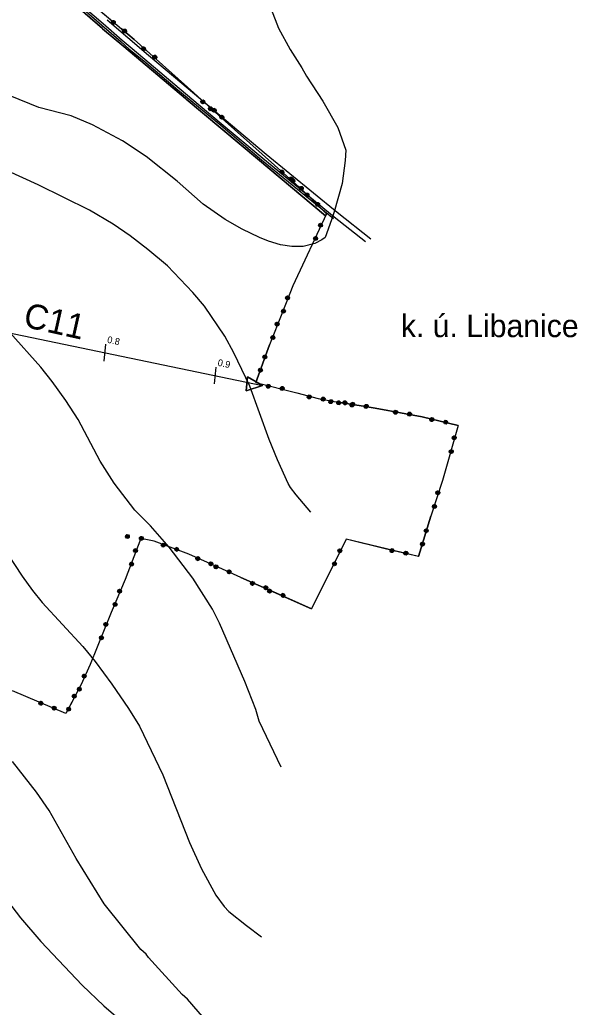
# Model space of a CAD drawing. Extents: x -645676 to -642474, y -1077513 to -1072613.
# Drawn here: x -642993 to -642499, y -1074361 to -1073486 of the extents above; entities that cross this region are included whole.
import ezdxf

# ---------------------------------------------------------------- set-up
doc = ezdxf.new("R2010")
doc.units = 0
for name, color, linetype in [('katastr_ln___zem____popis', 7, 'Continuous'), ('KULTURY_STAV', 7, 'Continuous'), ('OBVOD_PU', 7, 'Continuous'), ('P__kop___st_vaj_c_', 7, 'Continuous'), ('PC_NAVRH', 7, 'Continuous'), ('PC_POPIS_NAVRH', 7, 'Continuous'), ('PC_STAN_NAVRH', 7, 'Continuous'), ('Silnice_II__t__dy_a_III__t__dy', 7, 'Continuous'), ('SPRAV_HR_STAV', 7, 'Continuous'), ('VRSTEVNICE', 7, 'Continuous')]:
    doc.layers.add(name, color=color, linetype=linetype)

# ---------------------------------------------------------------- blocks, each defined once
blk = doc.blocks.new('$944')
blk.add_line((0, 1.5), (0, -1.5))
blk = doc.blocks.new('$920')
for points in [[(0, 0), (-2.8, 1.25), (-2.8, -1.25), (0, 0)], [(-2.8, 1.25), (0, 0), (-2.8, -1.25), (-2.8, 1.25)]]:
    blk.add_lwpolyline(points)
blk = doc.blocks.new('2$0620')
for points in [[(-1.07, 0.32), (-0.88, 0.13), (-0.88, -0.14), (-1.07, -0.33), (-1.34, -0.33), (-1.53, -0.14), (-1.53, 0.13), (-1.34, 0.32), (-1.07, 0.32), (-1.08, 0.28), (-1.32, 0.28), (-1.4, 0.2), (-1, 0.2), (-0.92, 0.12), (-1.48, 0.12), (-1.48, 0.04), (-0.92, 0.04), (-0.92, -0.04), (-1.48, -0.04), (-1.48, -0.12), (-0.92, -0.12), (-1, -0.2), (-1.4, -0.2), (-1.32, -0.28), (-1.08, -0.28)], [(1.43, 0.32), (1.62, 0.13), (1.62, -0.14), (1.43, -0.33), (1.16, -0.33), (0.97, -0.14), (0.97, 0.13), (1.16, 0.32), (1.43, 0.32), (1.4, 0.28), (1.16, 0.28), (1.08, 0.2), (1.48, 0.2), (1.56, 0.12), (1, 0.12), (1, 0.04), (1.56, 0.04), (1.56, -0.04), (1, -0.04), (1, -0.12), (1.56, -0.12), (1.48, -0.2), (1.08, -0.2), (1.16, -0.28), (1.4, -0.28)]]:
    blk.add_lwpolyline(points)

msp = doc.modelspace()

# ---------------------------------------------------------------- linework, layer by layer
at = {"layer": 'KULTURY_STAV'}
for points in [[(-642972.5, -1073447.63), (-642919.91, -1073493.56), (-642919.87, -1073493.59), (-642901.19, -1073509.35), (-642900.99, -1073509.52), (-642846.38, -1073555.54), (-642845.81, -1073556.02), (-642782.62, -1073608.9), (-642782.38, -1073609.11), (-642733.3, -1073650.5), (-642722.15, -1073659.46), (-642721.3, -1073657.64), (-642751.17, -1073721.72), (-642760.43, -1073745.06), (-642771.94, -1073773.87), (-642783.93, -1073807.14), (-642747.64, -1073816.53), (-642728.65, -1073821.54), (-642711.31, -1073824.82), (-642686.87, -1073828.69), (-642674.89, -1073830.57), (-642636.52, -1073837.75), (-642604.57, -1073845.43), (-642618.62, -1073894.26), (-642628.8, -1073925.8), (-642639.88, -1073961.58), (-642669.19, -1073954.61), (-642704.02, -1073946.33), (-642734.6, -1074008), (-642768.29, -1073993.02), (-642782.04, -1073986.91), (-642797.33, -1073980.11), (-642813.53, -1073972.91), (-642843.55, -1073959.52), (-642874.27, -1073947.97), (-642886.05, -1073945.72), (-642899.89, -1073981.87), (-642912.36, -1074011.3), (-642930.99, -1074057.3), (-642939.28, -1074075.5), (-642951.32, -1074098.58), (-642952.44, -1074100.73), (-642999.74, -1074080.7)], [(-642950.44, -1073453.5), (-642903.06, -1073493.73), (-642891.8, -1073503.23), (-642839.12, -1073550.41), (-642832.29, -1073556.56), (-642813.86, -1073573.17), (-642742.8, -1073636.35), (-642735.62, -1073643.46), (-642721.3, -1073657.64), (-642722.15, -1073659.46), (-642733.3, -1073650.5), (-642782.38, -1073609.11), (-642782.62, -1073608.9), (-642845.81, -1073556.02), (-642846.38, -1073555.54), (-642900.99, -1073509.52), (-642901.19, -1073509.35), (-642919.87, -1073493.59), (-642919.91, -1073493.56), (-642972.5, -1073447.63)]]:
    msp.add_lwpolyline(points, dxfattribs=at)
at = {"layer": 'OBVOD_PU'}
msp.add_lwpolyline([(-642950.44, -1073453.5), (-642903.06, -1073493.73), (-642891.8, -1073503.23), (-642839.12, -1073550.41), (-642832.29, -1073556.56), (-642813.86, -1073573.17), (-642742.8, -1073636.35), (-642735.62, -1073643.46), (-642721.3, -1073657.64), (-642751.17, -1073721.72), (-642760.43, -1073745.06), (-642771.94, -1073773.87), (-642783.93, -1073807.14), (-642747.64, -1073816.53), (-642728.65, -1073821.54), (-642711.31, -1073824.82), (-642686.87, -1073828.69), (-642674.89, -1073830.57), (-642636.52, -1073837.75), (-642604.57, -1073845.43), (-642618.62, -1073894.26), (-642628.8, -1073925.8), (-642639.88, -1073961.58), (-642704.02, -1073946.33), (-642734.6, -1074008), (-642782.04, -1073986.91), (-642797.33, -1073980.11), (-642813.53, -1073972.91), (-642843.55, -1073959.52), (-642874.27, -1073947.97), (-642886.05, -1073945.72), (-642899.89, -1073981.87), (-642912.36, -1074011.3), (-642930.99, -1074057.3), (-642939.28, -1074075.5), (-642952.44, -1074100.73), (-642999.74, -1074080.7)], dxfattribs=at)
at = {"layer": 'P__kop___st_vaj_c_'}
msp.add_lwpolyline([(-642946.02, -1073468.22), (-642920.53, -1073490.33), (-642903.65, -1073505.07), (-642896.31, -1073511.82), (-642883.41, -1073522.17), (-642853.25, -1073547.89), (-642815.13, -1073579.2), (-642778.88, -1073609.74), (-642715.19, -1073662.02)], dxfattribs=at)
at = {"layer": 'PC_NAVRH'}
msp.add_lwpolyline([(-643651.3, -1073746.65), (-643642.16, -1073747.03), (-643634.9, -1073748.9), (-643627.26, -1073738.26), (-643603.35, -1073720.23), (-643590.34, -1073707.33), (-643581.82, -1073694.43), (-643570.81, -1073681.9), (-643563.42, -1073670.01), (-643558.29, -1073648.59), (-643471.17, -1073665.87), (-643315.58, -1073698.56), (-643063.81, -1073750.46), (-642778.16, -1073809.87)], dxfattribs=at)
at = {"layer": 'Silnice_II__t__dy_a_III__t__dy'}
for p, q in [((-642919.47, -1073489.38), (-642945.46, -1073466.95)), ((-642915.88, -1073485.66), (-642879.26, -1073516.95)), ((-642902.44, -1073504.03), (-642919.47, -1073489.38)), ((-642895.41, -1073510.01), (-642902.44, -1073504.03)), ((-642882.36, -1073520.96), (-642895.41, -1073510.01)), ((-642852.1, -1073546.56), (-642882.36, -1073520.96)), ((-642879.26, -1073516.95), (-642849.69, -1073542.04)), ((-642814.6, -1073577.93), (-642852.1, -1073546.56)), ((-642849.69, -1073542.04), (-642812, -1073573.5)), ((-642812, -1073573.5), (-642774.73, -1073604.77)), ((-642777.87, -1073608.73), (-642814.6, -1073577.93)), ((-642774.73, -1073604.77), (-642712.02, -1073656.36)), ((-642714.55, -1073660.78), (-642777.87, -1073608.73)), ((-642686.73, -1073682.63), (-642714.55, -1073660.78)), ((-642712.02, -1073656.36), (-642682.01, -1073679.78))]:
    msp.add_line(p, q, dxfattribs=at)
at = {"layer": 'SPRAV_HR_STAV'}
for p, q in [((-642950.44, -1073453.5), (-642903.06, -1073493.73)), ((-642891.8, -1073503.23), (-642903.06, -1073493.73)), ((-642891.8, -1073503.23), (-642839.12, -1073550.41)), ((-642839.12, -1073550.41), (-642832.29, -1073556.56)), ((-642832.29, -1073556.56), (-642813.86, -1073573.17)), ((-642742.8, -1073636.35), (-642813.86, -1073573.17)), ((-642735.62, -1073643.46), (-642742.8, -1073636.35)), ((-642721.3, -1073657.64), (-642735.62, -1073643.46)), ((-642721.3, -1073657.64), (-642751.17, -1073721.72)), ((-642751.17, -1073721.72), (-642760.43, -1073745.06)), ((-642760.43, -1073745.06), (-642771.94, -1073773.87)), ((-642783.93, -1073807.14), (-642771.94, -1073773.87)), ((-642783.93, -1073807.14), (-642747.64, -1073816.53)), ((-642747.64, -1073816.53), (-642728.65, -1073821.54)), ((-642728.65, -1073821.54), (-642711.31, -1073824.82)), ((-642686.87, -1073828.69), (-642711.31, -1073824.82)), ((-642674.89, -1073830.57), (-642686.87, -1073828.69)), ((-642636.52, -1073837.75), (-642674.89, -1073830.57)), ((-642604.57, -1073845.43), (-642636.52, -1073837.75)), ((-642604.57, -1073845.43), (-642618.62, -1073894.26)), ((-642618.62, -1073894.26), (-642628.8, -1073925.8)), ((-642639.88, -1073961.58), (-642628.8, -1073925.8)), ((-642886.05, -1073945.72), (-642899.89, -1073981.87)), ((-642874.27, -1073947.97), (-642886.05, -1073945.72)), ((-642843.55, -1073959.52), (-642874.27, -1073947.97)), ((-642704.02, -1073946.33), (-642734.6, -1074008)), ((-642639.88, -1073961.58), (-642704.02, -1073946.33)), ((-642813.53, -1073972.91), (-642843.55, -1073959.52)), ((-642797.33, -1073980.11), (-642813.53, -1073972.91)), ((-642899.89, -1073981.87), (-642912.36, -1074011.3)), ((-642797.33, -1073980.11), (-642782.04, -1073986.91)), ((-642782.04, -1073986.91), (-642734.6, -1074008)), ((-642912.36, -1074011.3), (-642930.99, -1074057.3)), ((-642930.99, -1074057.3), (-642939.28, -1074075.5)), ((-642952.44, -1074100.73), (-642999.74, -1074080.7)), ((-642939.28, -1074075.5), (-642952.44, -1074100.73))]:
    msp.add_line(p, q, dxfattribs=at)
at = {"layer": 'VRSTEVNICE'}
for points in [[(-642770.53, -1073476.26), (-642763.83, -1073493.01), (-642753.58, -1073511.96), (-642743.06, -1073528.29), (-642739.19, -1073535.6), (-642724.67, -1073557.82), (-642711.36, -1073581.3), (-642704.27, -1073601.3), (-642704.79, -1073610.59), (-642707.44, -1073630.83), (-642714.41, -1073655.94), (-642716.83, -1073663.21), (-642722.66, -1073678.87), (-642725.38, -1073680.87), (-642731.65, -1073684.14), (-642741.9, -1073686.71), (-642752.15, -1073686.85), (-642762.27, -1073685.28), (-642772.7, -1073682.1), (-642780.64, -1073678.59), (-642796.02, -1073671.33), (-642811.12, -1073662.78), (-642830.77, -1073649.11), (-642853.7, -1073628.74), (-642881.19, -1073606.95), (-642902.27, -1073593.14), (-642928.76, -1073578.89), (-642947.84, -1073570.92), (-642976.33, -1073563.51), (-643001.96, -1073553.12)], [(-642735.18, -1073922.15), (-642748.28, -1073906.78), (-642753.15, -1073900.34), (-642755.29, -1073896.78), (-642764.9, -1073875.9), (-642772.24, -1073857.9), (-642789.18, -1073810.47), (-642803.43, -1073780.99), (-642811.4, -1073766.32), (-642829.63, -1073739.55), (-642839.74, -1073727.44), (-642862.39, -1073703.94), (-642879.62, -1073689.27), (-642895.29, -1073677.31), (-642910.38, -1073666.77), (-642931.61, -1073654.38), (-642976.9, -1073632.16), (-643004.24, -1073619.63)], [(-642761.39, -1074148.28), (-642780.92, -1074107.42), (-642784.06, -1074097.17), (-642793.74, -1074072.38), (-642816.24, -1074020.54), (-642822.51, -1074008.15), (-642839.89, -1073980.67), (-642860.82, -1073953.32), (-642877.49, -1073934.38), (-642891.19, -1073920.39), (-642909.67, -1073896.64), (-642921.92, -1073876.98), (-642941.57, -1073839.95), (-642952.4, -1073823.15), (-642964.5, -1073806.34), (-642974.76, -1073793.81), (-643002.1, -1073763.04)], [(-643340.18, -1073899.06), (-643332.66, -1073901.76), (-643282.53, -1073921.42), (-643259.74, -1073933.24), (-643241.51, -1073945.63), (-643227.56, -1073957.45), (-643214.6, -1073969.56), (-643206.34, -1073979.38), (-643188.53, -1074008.86), (-643169.16, -1074047.6), (-643160.48, -1074062.13), (-643136.41, -1074097.74), (-643116.61, -1074123.66), (-643104.93, -1074137.75), (-643074.88, -1074170.51), (-643046.97, -1074205.12), (-643008.8, -1074260.67), (-642992.7, -1074282.03), (-642974.76, -1074302.96), (-642937.87, -1074341.56), (-642918.65, -1074359.93), (-642874.35, -1074397.96), (-642851.28, -1074420.6), (-642800.28, -1074483.73)], [(-643018.62, -1073937.65), (-642991.28, -1073978.96), (-642982.02, -1073991.77), (-642973.33, -1074002.46), (-642937.44, -1074041.34), (-642926.48, -1074054.72), (-642911.67, -1074074.66), (-642896.85, -1074096.31), (-642887.03, -1074111.98), (-642866.38, -1074155.27), (-642842.73, -1074215.09), (-642832.3, -1074238.61), (-642819.38, -1074261.8), (-642811.97, -1074271.92), (-642807.84, -1074276.19), (-642792.24, -1074288.66), (-642778.85, -1074298.89)], [(-642825.71, -1074376.01), (-642844.73, -1074354.09), (-642849.29, -1074349.82), (-642879.19, -1074317.21), (-642881.33, -1074314.22), (-642885.95, -1074309.84), (-642918.5, -1074269.35), (-642943.43, -1074229.33), (-642967.21, -1074186.89), (-642978.6, -1074170.37), (-642999.83, -1074143.17)]]:
    msp.add_lwpolyline(points, dxfattribs=at)

# ---------------------------------------------------------------- block references
at = {"layer": 'PC_STAN_NAVRH', "xscale": 5.000000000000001, "yscale": 5, "rotation": -5.67241100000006}
for name, p in [('$944', (-642917.98, -1073780.79)), ('$944', (-642820.07, -1073801.15)), ('$920', (-642778.16, -1073809.87))]:
    msp.add_blockref(name, p, dxfattribs=at)
at = {"layer": 'SPRAV_HR_STAV'}
for p, xscale, yscale, rotation in [((-642905.18, -1073491.95), 5, 5, 142.286626), ((-642878.76, -1073514.91), 4.999999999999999, 5, -36.29468500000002), ((-642826.12, -1073562.12), 5, 5, -36.45099100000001), ((-642819.29, -1073568.28), 5, 5, -36.47700900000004), ((-642755.88, -1073624.72), 5, 5, 140.774284), ((-642748.05, -1073631.15), 5, 5, 137.64176), ((-642733.74, -1073645.33), 4.999999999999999, 5, 137.642552), ((-642728.69, -1073673.5), 5, 5.000000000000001, -110.715737), ((-642757.62, -1073737.99), 5, 5, -107.305695), ((-642766.92, -1073761.31), 5.000000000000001, 4.999999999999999, -107.44510000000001), ((-642778, -1073790.68), 5, 4.999999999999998, 71.406515), ((-642766.99, -1073811.52), 5, 5.000000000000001, -8.477077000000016), ((-642730.72, -1073820.99), 5, 4.999999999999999, -8.753967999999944), ((-642711.45, -1073824.79), 5, 5.000000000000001, -4.615157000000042), ((-642704.15, -1073825.95), 5, 5, 173.986641), ((-642692.18, -1073827.86), 5, 4.999999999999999, 174.067351), ((-642653.72, -1073834.53), 5, 5, 172.357688), ((-642621.59, -1073841.34), 5, 4.999999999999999, 169.389614), ((-642609.41, -1073862.25), 4.999999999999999, 5.000000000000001, -101.62005900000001), ((-642624, -1073910.91), 5, 5.000000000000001, -103.48805700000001), ((-642634.7, -1073944.86), 5.000000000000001, 5, 74.064298), ((-642891.46, -1073944.69), 5, 4.999999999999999, 172.139519), ((-642859.93, -1073953.36), 5, 5, 162.176889), ((-642892.31, -1073962.06), 5, 4.999999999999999, -106.602555), ((-642711.79, -1073962.01), 4.999999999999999, 4.999999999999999, -112.123157), ((-642656.91, -1073957.53), 4.999999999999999, 4.999999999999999, 169.533786), ((-642829.51, -1073965.78), 4.999999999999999, 4.999999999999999, 158.68345399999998), ((-642813.32, -1073973), 5.000000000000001, 4.999999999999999, 158.760884), ((-642781.34, -1073987.22), 5, 5.000000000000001, -18.111667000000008), ((-642906.72, -1073997.98), 5, 5, -108.651599), ((-642766.05, -1073994.02), 4.999999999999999, 4.999999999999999, -18.103216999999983), ((-642918.93, -1074027.52), 5, 5, -107.72038000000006), ((-642938.24, -1074073.23), 5, 5, -110.20403900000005), ((-642968.55, -1074093.91), 5.000000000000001, 4.999999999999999, 159.789951), ((-642947.37, -1074091.02), 5, 5, -113.31497900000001)]:
    msp.add_blockref('2$0620', p, dxfattribs=dict(at, xscale=xscale, yscale=yscale, rotation=rotation))

# ---------------------------------------------------------------- texts
at = {"layer": 'katastr_ln___zem____popis'}
msp.add_text('k. ú. Libanice', height=20, dxfattribs=at).set_placement((-642655.39, -1073767.07))
at = {"layer": 'PC_POPIS_NAVRH'}
msp.add_text('C11', height=22, rotation=347.384, dxfattribs=at).set_placement((-642991.11, -1073757.59))
at = {"layer": 'PC_STAN_NAVRH'}
for s, p in [('0.8', (-642916.15, -1073771.97)), ('0.9', (-642818.24, -1073792.34))]:
    msp.add_text(s, height=6, rotation=348.244, dxfattribs=at).set_placement(p)

doc.saveas('drawing.dxf')
